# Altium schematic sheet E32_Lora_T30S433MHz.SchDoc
size A4; Organization: Q-Tech Design; Address1: Da Nang City; Address2: Viet Nam; DocumentNumber: 3; SheetNumber: 3; SheetTotal: 7
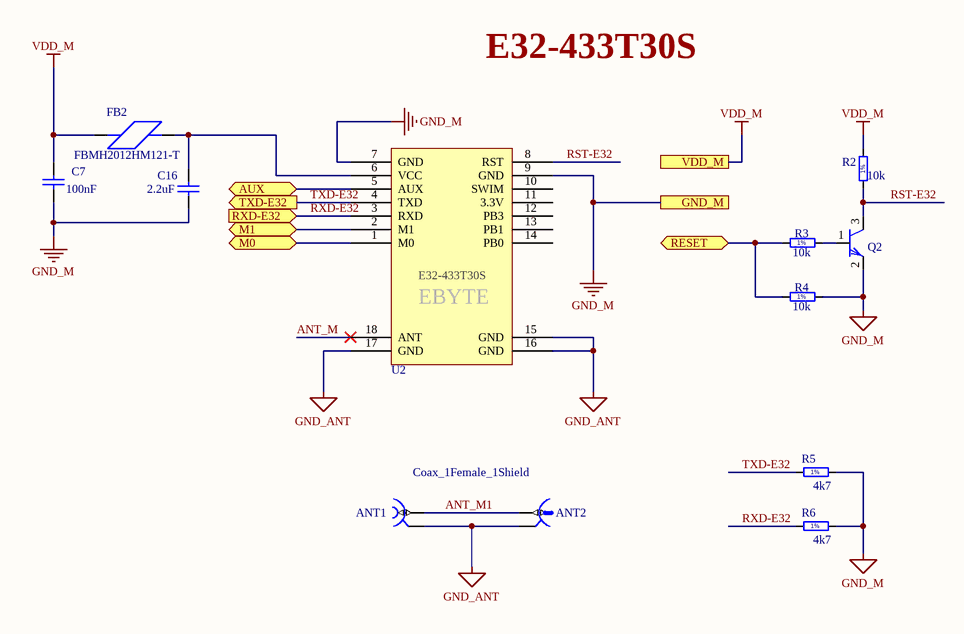
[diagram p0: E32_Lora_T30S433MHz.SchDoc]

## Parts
ANT1  Coax_1Female_1Shield  [HUBER-SUHNER_85 SMA-50-0-101/111 NE]
ANT2  U.FL  [HIROSE_U.FL-R-SMT-1(10)]  (value not drawn)
C7  100nF  [CAPC1608X87N]
C16  2.2uF  [CAPC1608X87N]
FB2  Manufacturer Part Number: FBMH2012HM121-T  [CHIP_0805]  (hidden comment: Ferrite bead Case 0805)
Q2  C1815  [SOT23-3]  (value not drawn)
R2  10k  [RESC1608X55N]
R3  10k  [RESC1608X55N]
R4  10k  [RESC1608X55N]
R5  4k7  [RESC1608X55N]
R6  4k7  [RESC1608X55N]
U2  E32-T30S  [E32-T30S]  (value not drawn)

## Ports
AUX (bidir), GND_M, M0 (bidir), M1 (bidir), RESET (bidir), RXD-E32 (in), TXD-E32 (out), VDD_M

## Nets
GND_ANT: ANT1.2 ANT2.2 U2.15(GND) U2.16(GND) U2.17(GND)
GND_M: C7.1 C16.1 Q2.2(E) R4.1 R5.2 R6.2 U2.7(GND) U2.9(GND) ; port GND_M
VDD_M: C7.2 FB2.1 R2.2 ; port VDD_M
ANT_M: U2.18(ANT)
ANT_M1: ANT1.1 ANT2.1
AUX: U2.5(AUX) ; port AUX
M0: U2.1(M0) ; port M0
M1: U2.2(M1) ; port M1
RESET: R3.1 R4.2 ; port RESET
RST-E32: Q2.3(C) R2.1 U2.8(RST)
RXD-E32: R6.1 U2.3(RXD) ; port RXD-E32
TXD-E32: R5.1 U2.4(TXD) ; port TXD-E32
NetC16_2: C16.2 FB2.2 U2.6(VCC)
NetQ2_1: Q2.1(B) R3.2

Not connected (* = marked no-connect by the designer): U2 10(SWIM) 11(3.3V) 12(PB3) 13(PB1) 14(PB0)

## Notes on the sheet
- E32-433T30S

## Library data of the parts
ANT1 = HUBER-SUHNER_85_SMA-50-0-101/111_NE: Part Description: SMA 50 Ohms Right Angle PCB Jack; Manufacturer: HUBER+SUHNER; Table: Miscellaneous
ANT2 = HIROSE_U.FL-R-SMT-1(10): Part Description: Up to 6GHz Ultra Small Surface Mount Male Coaxial Connectors U.FL Series; Manufacturer: HIROSE (HRS); Table: Miscellaneous
C7 = CC0603_100NF_50V_10%_X7R: Non-polarised capacitor; Part Description: SMD Multilayer Chip Ceramic Capacitor; Manufacturer: GENERIC; Manufacturer1 Part Number: 223858615649; Voltage: 50V; TC: X7R; Tolerance: ±10%; Table: Capacitors SMD
C16 = CC0603_2.2UF_16V_10%_X5R: Non-polarised capacitor; Part Description: SMD Multilayer Chip Ceramic Capacitor; Manufacturer: GENERIC; Manufacturer1 Part Number: CC0603KRX5R7BB225; Voltage: 16V; TC: X5R; Tolerance: ±10%; Table: Capacitors SMD
FB2 = FERRITE_0805
Q2 = 2SC1815: PSpiceTemplate: Q^@REFDES %c %b %e @MODEL; Vendor: Digikey
R2 = R0603_4K7_1%_0.1W_100PPM: Resistor - 1%; Part Description: General Purpose Thick Film Chip Resistor; Manufacturer: GENERIC; Manufacturer1 Part Number: NRC06F4701TRF; Value: 4k7; Power: 0.1W; TC: ±100ppm/°C; Table: Resistors SMD
R3 R4 = R0603_1K_1%_0.1W_100PPM: Resistor - 1%; Part Description: General Purpose Thick Film Chip Resistor; Manufacturer: GENERIC; Manufacturer1 Part Number: NRC06F1001TRF; Value: 1k; Power: 0.1W; TC: ±100ppm/°C; Table: Resistors SMD
R5 R6 = R0603_10K_1%_0.1W_100PPM: Resistor - 1%; Part Description: General Purpose Thick Film Chip Resistor; Manufacturer: GENERIC; Manufacturer1 Part Number: NRC06F1002TRF; Value: 10k; Power: 0.1W; TC: ±100ppm/°C; Table: Resistors SMD
U2 = E32-433T30S: Lora Ebyte E32-T30S Module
